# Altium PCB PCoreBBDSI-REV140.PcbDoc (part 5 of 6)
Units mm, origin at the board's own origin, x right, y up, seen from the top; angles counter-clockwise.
Board outline 100 x 72 mm, 6 copper layers (Top Layer, Int1 (GND), Int2 (Sign), Int3 (Sign), Int4 (GND), Bottom Layer), stack 1.551 mm thick; 358 components, 403 nets, 1535 pads, 844 vias.
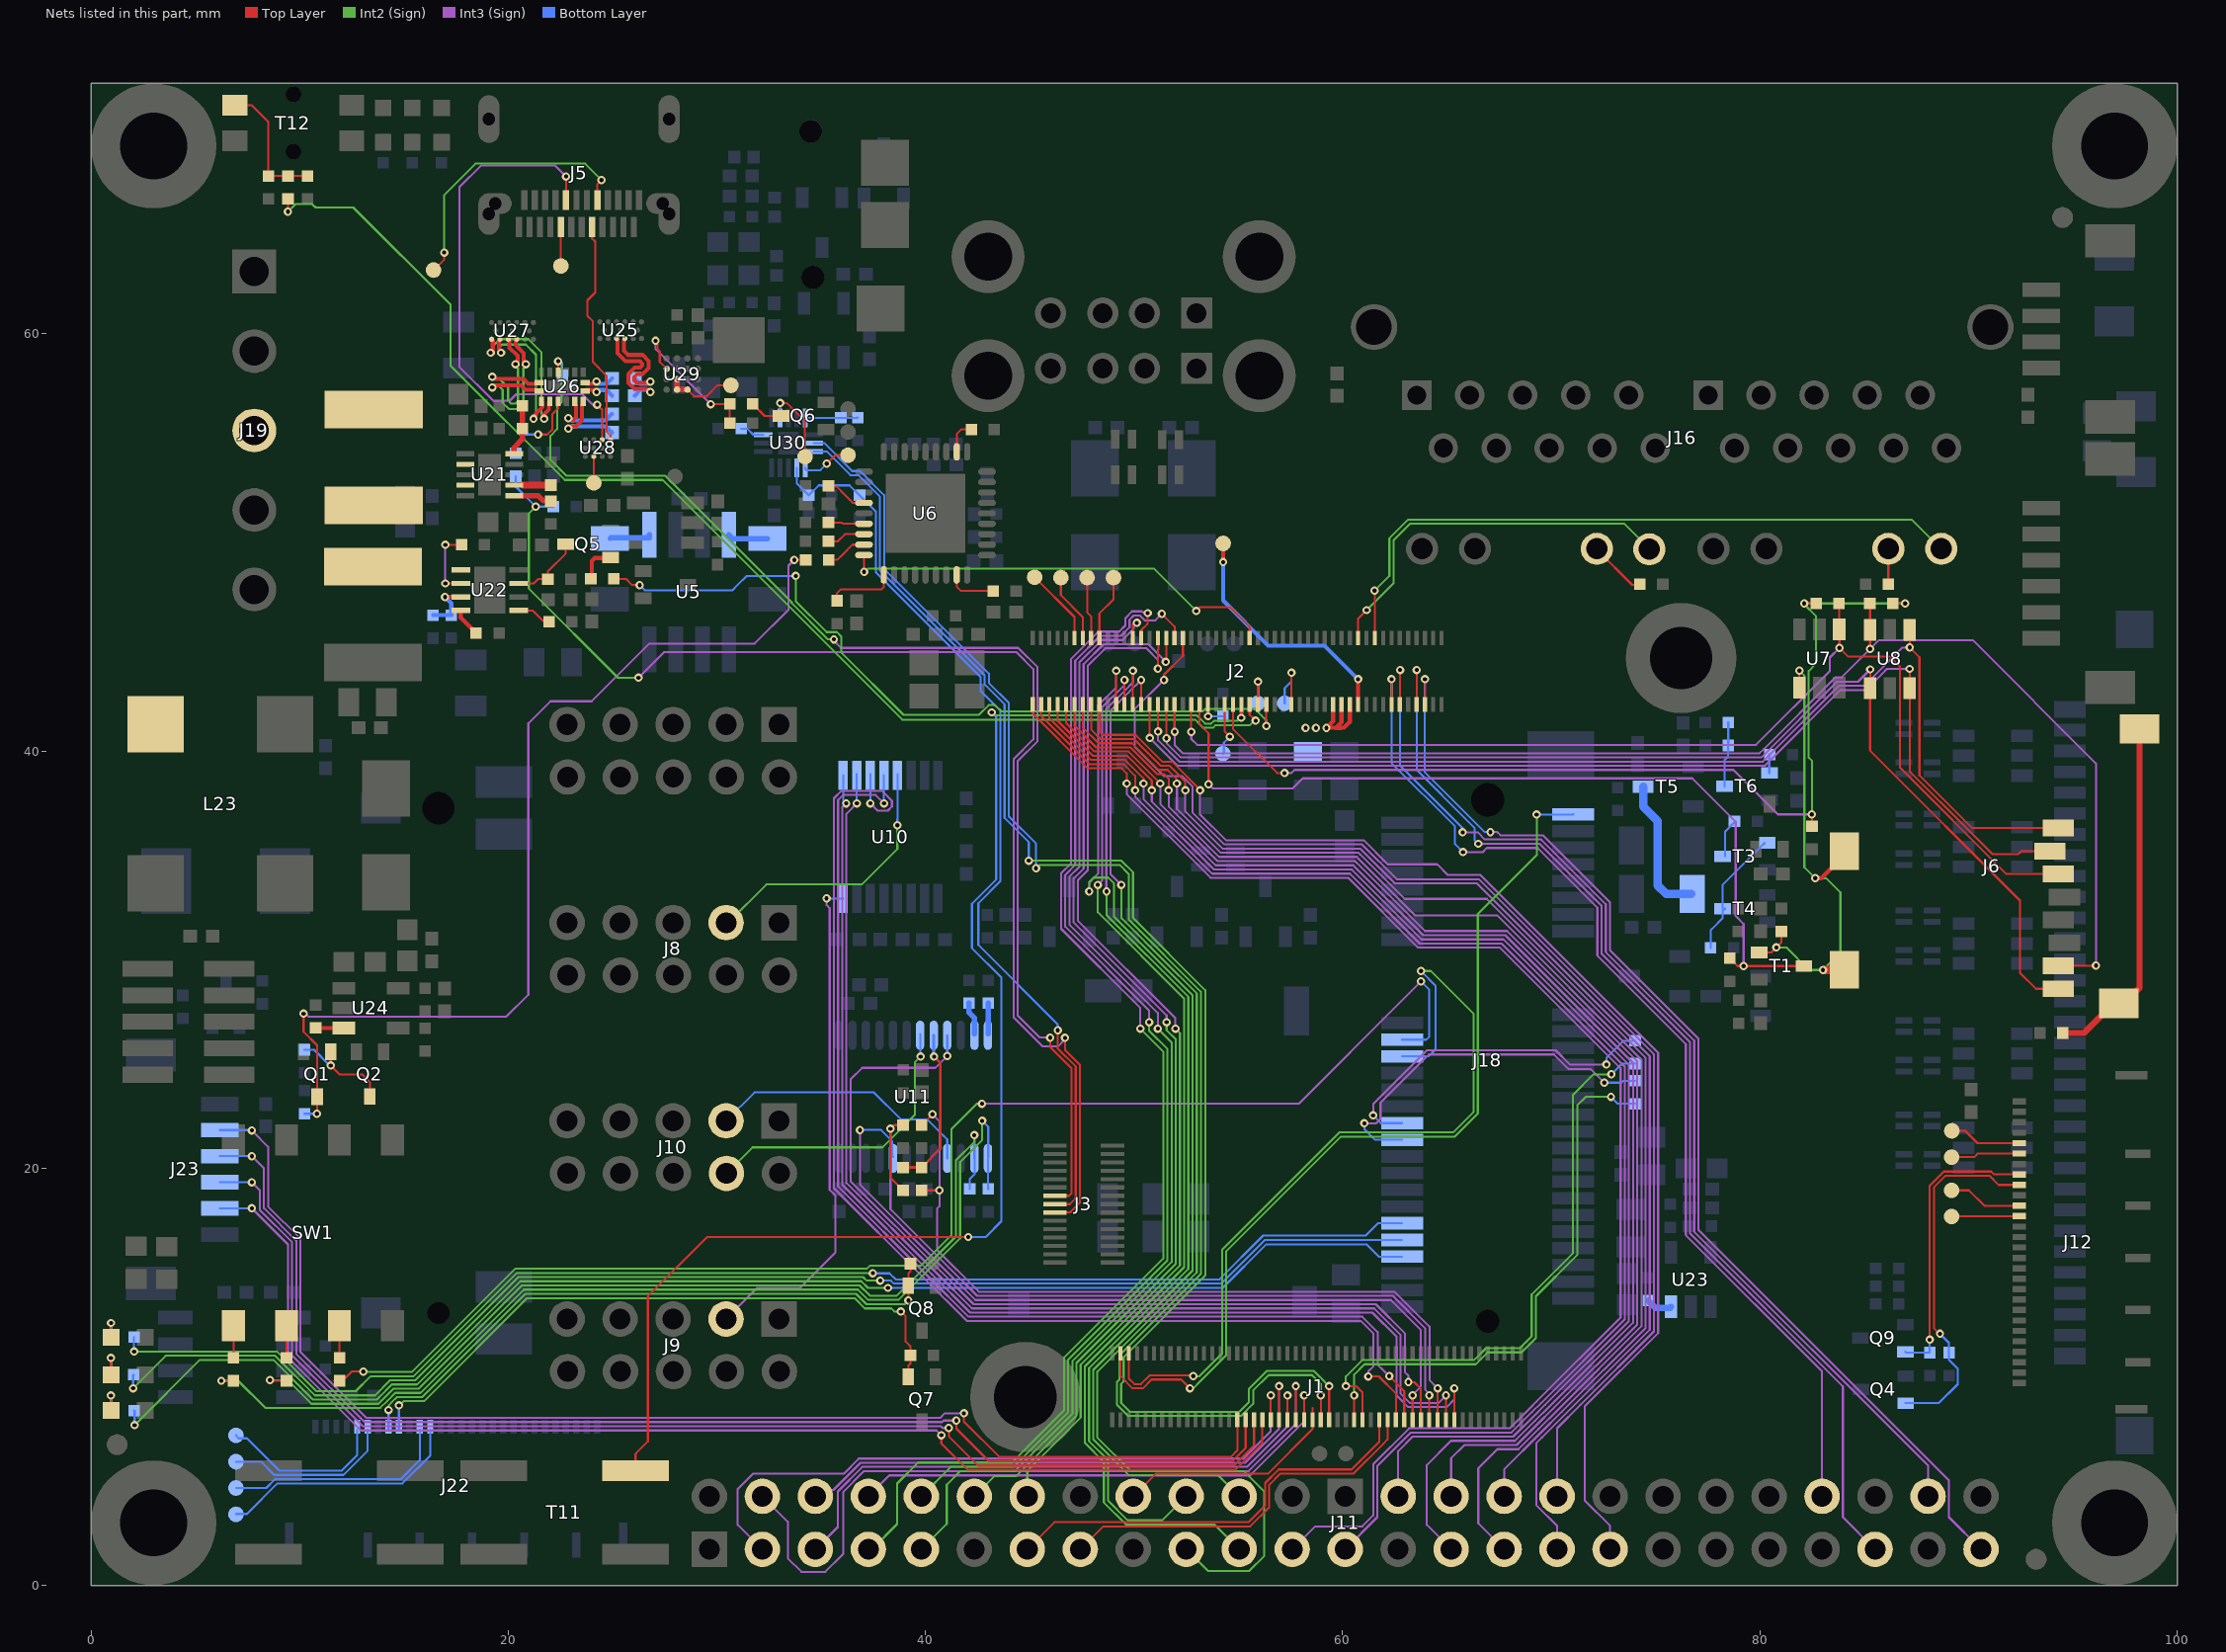
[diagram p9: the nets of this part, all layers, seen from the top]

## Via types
v1: diameter 0.4, hole 0.2, Top Layer to Bottom Layer, tented both sides, 716 vias
v2: diameter 0.5, hole 0.3, Top Layer to Bottom Layer, tented both sides, 102 vias
v3: diameter 0.4, hole 0.2, Top Layer to Bottom Layer, tented bottom, 16 vias
v4: diameter 0.9, hole 0.9, Top Layer to Bottom Layer, 6 vias
v5: diameter 0.5, hole 0.5, Top Layer to Bottom Layer, 2 vias
v6: diameter 3.2, hole 3.2, Top Layer to Bottom Layer, tented both sides, 2 vias

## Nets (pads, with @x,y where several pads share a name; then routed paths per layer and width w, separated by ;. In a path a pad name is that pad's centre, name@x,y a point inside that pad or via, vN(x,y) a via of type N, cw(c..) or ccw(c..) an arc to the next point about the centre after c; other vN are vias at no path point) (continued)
NetJ1_18: J1.18 U10.9 | length 57.2
  Top Layer w0.1: J1.18@65.348,8.229 65.35,8.231 v1(65.35,9.45)
  Int3 (Sign) w0.1: 36.01,37.24 36.01,33.241 36.01,32.619 36.01,19.212 40.31,14.913 42.143,13.08 61.42,13.08 62.58,11.92 62.58,9.102 63.132,8.55 64.98,8.55 65.35,8.92 v1(65.35,9.45) ; 36.01,37.24 36.01,37.3 v1(36.2,37.49)
  Bottom Layer w0.1: U10.9@36.055,38.83 36.055,38.42 36.055,37.462 36.172,37.462 v1(36.2,37.49)
NetJ1_20: J1.20 U10.10 | length 55.6
  Top Layer w0.1: J1.20@64.948,8.229 64.95,8.231 v1(64.95,9.11)
  Int3 (Sign) w0.1: v1(36.71,37.49) 36.21,36.99 36.21,33.324 36.21,32.536 36.21,19.295 40.51,14.996 42.225,13.28 61.457,13.28 61.503,13.28 62.78,12.003 62.78,11.957 62.78,11.858 62.78,9.185 63.215,8.75 64.6,8.75 64.95,9.1 v1(64.95,9.11)
  Bottom Layer w0.1: U10.10@36.705,38.88 36.705,37.635 36.71,37.63 v1(36.71,37.49)
NetJ1_22: J1.22 R39.1 R41.1 | length 37.8
  Top Layer w0.1: R41.1@39.815,18.936 v1(40.67,18.936) ; R39.1@39.815,22.064 39.815,22.075 v1(40.33,22.59) ; J1.22@64.548,8.229 64.55,8.231 v1(64.55,9.45)
  Int3 (Sign) w0.1: v1(40.33,22.59) 40.67,22.25 v1(40.67,18.936) 40.67,18.175 40.55,18.055 40.55,16.087 42.557,14.08 62.48,14.08 64.16,12.4 64.16,9.84 v1(64.55,9.45)
NetJ1_24: J1.24 R40.1 R42.1 | length 39.9
  Top Layer w0.1: R40.1@38.925,18.936 38.32,19.541 v1(38.32,21.89) 38.494,22.064 R42.1@38.925,22.064 ; J1.24@64.148,8.229 64.15,8.231 v1(64.15,9.11)
  Int3 (Sign) w0.1: v1(38.32,21.89) 38.32,18.034 41.11,15.244 42.474,13.88 62.397,13.88 63.95,12.327 63.95,9.391 64.15,9.191 v1(64.15,9.11)
NetJ1_26: J1.26 U11.9 | length 44.9
  Top Layer w0.1: v1(63.15,9.75) 63.162,9.738 63.433,9.738 63.75,9.421 J1.26@63.75,8.231
  Int3 (Sign) w0.1: v1(41.04,25.38) 40.469,24.809 36.964,24.809 36.41,24.255 36.41,19.378 40.71,15.079 42.308,13.48 61.54,13.48 61.586,13.48 62.98,12.086 62.98,12.04 62.98,10.224 63.15,10.055 v1(63.15,9.75)
  Bottom Layer w0.1: v1(41.04,25.38) 41.045,25.385 U11.9@41.045,26.37
NetJ1_28: J1.28 U11.20 | length 39.1
  Top Layer w0.1: J1.28@63.348,8.229 63.35,8.231 v1(63.35,9.11)
  Int3 (Sign) w0.1: v1(36.86,21.83) 36.855,21.825 36.855,19.216 40.91,15.161 42.391,13.68 62.314,13.68 63.75,12.244 63.75,9.54 63.35,9.14 v1(63.35,9.11)
  Bottom Layer w0.1: v1(36.86,21.83) 37.87,21.83 38.41,21.29 38.41,20.585 U11.20@38.455,20.54
NetJ1_30: J1.30 U10.12 | length 55.6
  Top Layer w0.1: v1(62.23,10.03) 62.95,9.31 62.95,8.501 J1.30@62.95,8.16
  Int3 (Sign) w0.1: v1(38.01,37.49) 37.61,37.89 36.054,37.89 35.81,37.645 35.81,37.323 35.81,33.158 35.81,32.702 35.81,19.129 40.109,14.83 42.06,12.88 60.941,12.88 61.674,12.147 61.674,10.586 61.93,10.33 v1(62.23,10.03)
  Bottom Layer w0.1: U10.12@38.005,38.83 U10.12@38.005,38.83 38.006,37.684 38.01,37.68 v1(38.01,37.49)
NetJ1_32: J1.32 U10.11 | length 58.3
  Top Layer w0.1: v1(61.23,10.02) 61.73,10.02 62.55,9.2 J1.32@62.55,8.16
  Int3 (Sign) w0.1: v1(37.36,37.49) 37.71,37.14 37.865,37.14 38.155,37.14 38.19,37.14 38.39,37.34 38.39,37.61 37.91,38.09 35.971,38.09 35.61,37.728 35.61,33.075 35.61,32.785 35.61,19.046 39.909,14.747 41.977,12.68 60.858,12.68 61.474,12.064 61.474,10.514 61.23,10.27 v1(61.23,10.02)
  Bottom Layer w0.1: U10.11@37.355,38.88 37.355,37.635 37.36,37.63 v1(37.36,37.49)
NetJ1_34: J1.34 J11.15 | length 18.5
  Top Layer w0.1: J11.15@47.42,1.73 48.52,2.83 55.563,2.83 56.48,3.747 56.48,4.827 57.013,5.36 60.513,5.36 61.95,6.797 62.15,6.997 J1.34@62.15,7.94 ; J1.34@62.148,8.229 J1.34@62.15,8.231
NetJ1_36: J1.36 J11.13 | length 20.7
  Top Layer w0.1: J11.13@44.88,1.73 46.18,3.03 55.48,3.03 56.28,3.83 56.28,4.91 56.93,5.56 60.43,5.56 61.75,6.88 J1.36@61.75,7.94 ; J1.36@61.748,8.229 J1.36@61.75,8.231
NetJ1_40: J1.40 R55.2 | length 28.4
  Top Layer w0.1: v1(60.15,9.55) 60.65,9.55 60.95,9.25 J1.40@60.95,8.231 ; J1.40@60.948,8.229 J1.40@60.95,8.231 ; J1.40@60.95,7.94 J1.40@60.95,8.231
  Int2 (Sign) w0.1: v1(60.15,9.55) 60.15,10.01 60.94,10.8 66.296,10.8 66.866,11.37 68.493,11.37 69.06,11.938 69.06,13.943 71.04,15.923 71.04,23.52 72.02,24.5 v1(72.88,24.5)
  Bottom Layer w0.1: v1(72.88,24.5) 73.39,25.01 R55.2@74.02,25.01
NetJ1_42: J1.42 R56.2 | length 26.4
  Top Layer w0.1: J1.42@60.548,8.229 60.55,8.231 v1(60.55,9.11)
  Int2 (Sign) w0.1: v1(60.55,9.11) 60.55,10.11 61.04,10.6 66.379,10.6 66.949,11.17 68.413,11.17 68.575,11.17 69.26,11.855 69.26,13.86 71.24,15.84 71.24,23.01 71.65,23.42 v1(72.86,23.42)
  Bottom Layer w0.1: v1(72.86,23.42) 73.19,23.09 R56.2@74.02,23.09
NetJ1_48: J1.48 U30.8 | length 71.2
  Top Layer w0.1: J1.48@59.35,8.231 59.348,8.229 59.348,9.548 v1(59.35,9.55)
  Int2 (Sign) w0.1: v1(44.95,34.74) 49.39,34.74 49.95,34.18 49.95,31.995 53.41,28.535 53.41,14.851 49.5,10.941 49.5,9.782 49.377,9.659 49.377,8.746 49.803,8.32 55.037,8.32 55.51,8.793 55.51,9.43 56.363,10.283 58.617,10.283 v1(59.35,9.55)
  Bottom Layer w0.1: U30.8@34.63,54.36 35.264,54.36 36.404,53.22 36.78,53.22 37.82,52.18 37.82,51.52 37.82,50.973 37.82,48.647 42.84,43.627 42.84,43.182 43.79,42.232 43.79,36.79 44.95,35.63 v1(44.95,34.74)
NetJ1_50: J1.50 U30.7 | length 71.3
  Top Layer w0.1: J1.50@58.948,8.229 58.95,8.231 v1(58.95,9.11)
  Int2 (Sign) w0.1: v1(45.3,34.38) 45.302,34.38 45.462,34.54 49.307,34.54 49.75,34.097 49.75,31.912 53.2,28.461 53.2,14.924 49.3,11.024 49.3,9.865 49.177,9.742 49.177,8.663 49.72,8.12 55.12,8.12 55.71,8.71 55.71,9.347 56.445,10.082 58.534,10.082 58.95,9.667 v1(58.95,9.11)
  Bottom Layer w0.1: U30.7@34.63,54.76 35.147,54.76 36.487,53.42 36.863,53.42 38.02,52.263 38.02,48.73 43.04,43.71 43.04,43.265 43.99,42.315 43.99,36.873 45.3,35.563 v1(45.3,34.38)
NetJ1_52: J1.52 J11.18 | length 10.9
  Top Layer w0.1: J11.18@49.96,4.27 51.04,5.35 56.41,5.35 58.55,7.49 58.55,7.628 J1.52@58.55,7.94 ; J1.52@58.548,7.94 58.548,8.501
NetJ1_54: J1.54 J11.8 | length 24.8
  Top Layer w0.1: J1.54@58.148,8.229 58.148,8.75 ; v1@58.148,9.048 58.148,8.75 ; v1(58.15,9.11) 58.15,8.752 58.148,8.75
  Int3 (Sign) w0.1: J11.8@37.26,4.27 38.262,5.272 39.05,5.272 ; 39.05,5.272 55.562,5.272 58.15,7.86 v1(58.15,9.11)
  Bottom Layer w0.1: J11.8@37.25,4.28 J11.8@37.26,4.27
NetJ1_56: J1.56 J11.4 | length 35.9
  Top Layer w0.1: J1.56@57.748,8.229 57.748,9.548 v1(57.75,9.55)
  Int3 (Sign) w0.1: J11.4@32.18,4.27 33.4,3.05 33.4,1.3 34.05,0.65 35.2,0.65 36.05,1.5 36.05,4.474 37.056,5.48 40.409,5.48 55.487,5.48 57.75,7.743 v1(57.75,9.55)
NetJ1_58: J1.58 J11.5 | length 28.4
  Top Layer w0.1: J1.58@57.348,8.229 57.348,9.098 v1(57.35,9.1)
  Int3 (Sign) w0.1: J11.5@34.72,1.73 34.73,1.73 35.8,2.8 35.8,4.507 36.973,5.68 40.492,5.68 55.404,5.68 57.35,7.626 v1(57.35,9.1)
NetJ1_60: J1.60 J11.6 | length 26.9
  Top Layer w0.1: J1.60@56.948,8.229 56.95,8.231 v1(56.95,9.55)
  Int3 (Sign) w0.1: J11.6@34.72,4.27 35.026,4.576 35.586,4.576 36.89,5.88 40.575,5.88 55.321,5.88 56.95,7.509 v1(56.95,9.55)
NetJ1_62: J1.62 J11.3 | length 36.8
  Top Layer w0.1: 56.548,8.752 56.548,8.229 56.55,8.231 v1(56.55,9.11) ; 56.55,8.752 v1(56.55,9.11) ; 56.55,8.752 v1(56.55,9.11) ; 56.55,8.752 v1(56.55,9.11) ; 56.55,8.752 v1(56.55,9.11) ; 56.55,8.752 v1(56.55,9.11) ; 56.55,8.752 v1(56.55,9.11) ; 56.55,8.752 v1(56.55,9.11) ; 56.55,8.752 v1(56.55,9.11) ; 56.55,8.752 v1(56.55,9.11) ; 56.55,8.752 v1(56.55,9.11)
  Int3 (Sign) w0.1: J11.3@32.18,1.73 32.17,1.73 31,2.9 31,4.62 31.74,5.36 36.087,5.36 36.807,6.08 40.657,6.08 55.238,6.08 56.55,7.392 v1(56.55,9.11)
NetJ1_64: J1.64 J23.5 | length 60.3
  Top Layer w0.1: v1(40.76,7.2) 40.76,6.8 42.01,5.55 54.877,5.55 56.148,6.821 J1.64@56.148,8.229
  Int3 (Sign) w0.1: v1(7.71,18.075) 9.44,16.345 9.44,10.936 10.05,10.326 10.05,10.323 12.943,7.43 40.53,7.43 v1(40.76,7.2)
  Bottom Layer w0.1: J23.5@6.17,18.075 7.47,18.075
NetJ1_66: J1.66 J23.4 | length 60.9
  Top Layer w0.1: v1(41.12,7.55) 41.12,7.15 42.52,5.75 54.794,5.75 55.748,6.704 J1.66@55.748,8.229
  Int3 (Sign) w0.1: v1(7.71,19.325) 8.09,18.945 8.09,17.994 9.64,16.444 9.64,11.019 13.029,7.63 40.74,7.63 40.82,7.55 v1(41.12,7.55)
  Bottom Layer w0.1: J23.4@6.17,19.325 7.47,19.325
NetJ1_68: J1.68 J23.3 | length 61.5
  Top Layer w0.1: v1(41.48,7.9) 41.48,7.515 43.045,5.95 54.711,5.95 55.348,6.587 J1.68@55.348,8.229
  Int3 (Sign) w0.1: v1(7.71,20.575) 8.29,19.995 8.29,18.077 9.84,16.527 9.84,11.102 13.112,7.83 40.793,7.83 40.863,7.9 v1(41.48,7.9)
  Bottom Layer w0.1: J23.3@6.17,20.575 7.47,20.575
NetJ1_70: J1.70 J23.2 | length 62.4
  Top Layer w0.1: v1(41.84,8.25) 41.84,7.862 43.552,6.15 54.628,6.15 54.948,6.47 J1.70@54.948,8.229
  Int3 (Sign) w0.1: v1(7.71,21.81) 8.49,21.03 8.49,18.16 10.04,16.61 10.04,11.185 13.195,8.03 40.71,8.03 40.93,8.25 v1(41.84,8.25)
  Bottom Layer w0.1: J23.2@6.17,21.825 7.695,21.825 v1(7.71,21.81)
NetJ1_95: J1.95 J18.22 | length 40.1
  Top Layer w0.1: J1.95@49.75,11.12 49.75,9.915 50.015,9.65 50.335,9.65 50.755,10.07 52.83,10.07 52.84,10.08 52.84,10.032 v1(52.838,10.03)
  Int2 (Sign) w0.1: v1(52.838,10.03) 53.13,10.03 54.22,11.12 54.22,16.1 59.835,21.715 65.295,21.715 66.28,22.7 66.28,27.39 64.22,29.45 v1(63.75,29.45)
  Bottom Layer w0.1: J18.22@62.85,25.36 64.11,25.36 64.45,25.7 64.45,28.749 v1(63.75,29.45)
NetJ1_97: J1.97 J18.1 | length 44.4
  Top Layer w0.1: J1.97@49.35,11.12 49.35,10.032 49.932,9.45 50.418,9.45 50.838,9.87 52.26,9.87 v1(52.68,9.45)
  Int2 (Sign) w0.1: v1(52.68,9.45) 52.833,9.45 53.213,9.83 54.42,11.037 54.42,16.017 59.918,21.515 65.378,21.515 66.48,22.617 66.48,32.186 69.3,35.006 v1(69.3,36.95)
  Bottom Layer w0.1: v1(69.3,36.95) 71.04,36.95 J18.1@71.05,36.96
NetJ2_6: J2.6 J11.49 | length 55.2
  Top Layer w0.1: 63.94,42.791 63.95,42.801 v1@63.95,43.44 ; J2.6@63.95,42.507 63.95,42.791
  Int3 (Sign) w0.1: v1(67.08,36.11) 67.41,36.11 67.56,35.96 69.589,35.96 72.81,32.739 72.81,30.442 77.05,26.202 77.05,17.079 ; 77.05,17.079 77.05,17.04 89.06,5.03 89.06,3.27 J11.49@90.6,1.73
  Bottom Layer w0.1: v1(63.94,43.44) 63.94,38.978 66.2,36.718 66.807,36.11 v1(67.08,36.11)
NetJ2_8: J2.8 J11.45 | length 54.3
  Top Layer w0.1: J2.8@63.538,42.519 63.55,42.531 63.55,43.44 v1(63.55,43.88)
  Int3 (Sign) w0.1: v1(66.5,35.55) 69.433,35.55 72.41,32.573 72.41,30.276 76.65,26.036 76.65,16.913 76.65,16.874 83.98,9.544 83.98,3.27 J11.45@85.52,1.73
  Bottom Layer w0.1: v1(63.55,43.88) 63.55,43.44 63.55,39.085 66,36.635 66.32,36.314 66.32,35.73 v1(66.5,35.55)
NetJ2_12: J2.12 J11.48 | length 53.5
  Top Layer w0.1: J2.12@62.738,42.519 62.75,42.531 v1(62.75,43.88)
  Int3 (Sign) w0.1: v1(65.75,36.1) 66.47,36.1 66.81,35.76 69.506,35.76 72.61,32.656 72.61,30.359 76.85,26.119 76.85,16.996 ; 76.85,16.996 76.85,16.957 88.06,5.747 J11.48@88.06,4.27
  Bottom Layer w0.1: v1(62.75,43.88) 62.75,39.31 65.75,36.31 v1(65.75,36.1)
NetJ2_14: J2.14 J11.44 | length 51.1
  Top Layer w0.1: J2.14@62.338,42.519 J2.14@62.34,42.517 ; v1(62.34,43.44) J2.14@62.34,42.517 ; J2.14@62.34,42.517 62.35,42.507 J2.14@62.34,42.517
  Int3 (Sign) w0.1: v1(65.77,35.15) 66.71,35.15 66.91,35.35 69.35,35.35 72.21,32.49 72.21,30.193 76.45,25.953 76.45,16.83 76.45,16.791 82.98,10.261 J11.44@82.98,4.27
  Bottom Layer w0.1: v1(62.34,43.44) 62.34,39.43 65.38,36.39 65.38,35.54 v1(65.77,35.15)
NetJ2_17: J2.17 J16.L14 | length 32.8
  Top Layer w0.1: v1(61.53,47.69) 61.538,47.682 J2.17@61.538,45.129
  Int2 (Sign) w0.1: v1(61.53,47.69) 61.53,47.68 62.24,48.39 62.24,50.193 63.137,51.09 87.275,51.09 J16.L14@88.695,49.67
NetJ2_21: J2.21 J16.R14 | length 18.8
  Top Layer w0.1: J2.21@60.738,45.129 60.738,46.338 v1(61.15,46.75)
  Int2 (Sign) w0.1: v1(61.15,46.75) 62.44,48.04 62.44,50.11 63.22,50.89 73.505,50.89 J16.R14@74.725,49.67
NetJ2_22: J2.22 TP1.1 | length 11.7
  Top Layer w0.2: v1(54.27,49.05) TP1.1@54.27,49.95 ; J2.22@60.738,42.519 v1(60.738,43.44)
  Bottom Layer w0.2: v1(54.27,49.05) 54.27,47.21 56.43,45.05 59.128,45.05 v1(60.738,43.44)
NetJ2_24: J2.24 J2.26 J2.28 R2.1 | length 5.3
  Top Layer w0.2: J2.28@59.54,42.45 59.54,41.42 v1(59.22,41.1) 59.23,41.11 59.67,41.11 ; J2.26@59.94,42.45 59.94,41.38 59.66,41.1 59.914,41.1 59.924,41.11 60.06,41.11 60.34,41.39 J2.24@60.34,42.45
  other v1: 58.22,41.1 58.72,41.1
NetJ2_38: J2.38 TP29.1 | length 3.1
  Top Layer w0.1: J2.38@57.54,42.23 v1@57.54,43.76
  Bottom Layer w0.1: TP29.1@57.22,42.29 57.22,43.01 57.54,43.33 v1@57.54,43.76
  other v1: 57.54,43.75
NetJ2_44: J2.44 R79.1 | length 37.9
  Top Layer w0.1: R79.1@25.06,48.25 25.64,48.25 25.94,47.95 v1(26.3,47.95) ; J2.44@56.338,42.519 56.338,41.2 v1(56.34,41.2)
  Int2 (Sign) w0.1: v1(33.782,48.387) 33.782,47.178 35.26,45.7 35.755,45.7 35.96,45.495 35.96,44.72 38.95,41.73 42.565,41.73 43.035,42.2 43.34,42.2 43.64,41.9 53.297,41.9 53.406,42.01 55.8,42.01 56.11,41.7 56.34,41.47 v1(56.34,41.2)
  Bottom Layer w0.1: v1(26.3,47.95) 26.56,47.69 30.728,47.69 30.988,47.95 31.425,48.387 v1(33.782,48.387)
NetJ2_46: J2.46 TP23.1 | length 2.1
  Top Layer w0.1: J2.46@55.94,42.23 v1(55.94,43.32)
  Bottom Layer w0.1: TP23.1@55.92,42.29 55.94,42.31 v1(55.94,43.32)
NetJ2_47: J2.47 U6.27 | length 21.5
  Top Layer w0.1: U6.27@37,49.39 37.084,49.306 37.06,49.282 v1(37.06,48.59) ; v1(52.98,46.71) 53.16,46.89 53.935,46.89 54.6,46.89 55.2,46.29 55.538,45.952 J2.47@55.538,45.129
  Int2 (Sign) w0.1: v1(37.06,48.59) 37.06,48.566 37.064,48.57 37.239,48.745 50.945,48.745 v1(52.98,46.71)
NetJ2_48: J2.48 R70.2 | length 60.6
  Top Layer w0.1: v1(9.44,65.85) R70.2@9.44,66.46 ; J2.48@55.54,42.517 55.538,42.519 55.538,41.742 v1(55.83,41.45)
  Int2 (Sign) w0.1: v1(9.44,65.85) 9.8,66.21 10.605,66.21 10.765,66.05 11.223,66.05 12.038,66.05 12.57,66.05 17.23,61.39 17.23,59.498 17.23,59.042 17.23,58.467 22.707,52.99 26.925,52.99 27.215,52.99 27.4,52.99 38.89,41.5 52.933,41.5 53.128,41.305 53.324,41.109 53.779,41.109 53.91,41.24 55.557,41.24 55.767,41.45 v1(55.83,41.45)
NetJ2_50: J2.50 T11.2 | length 65.8
  Top Layer w0.1: T11.2@26.1,5.5 26.1,6.31 26.695,6.905 26.695,13.865 29.53,16.7 v1(42.05,16.7) ; v1(55.13,41.59) 55.13,41.57 v1@55.14,41.56
  Top Layer w0.2: v1@55.14,41.56 J2.50@55.14,42.23 J2.50@55.14,42.45
  Int2 (Sign) w0.1: v1(43.18,41.85) 43.222,41.85 43.372,41.7 43.557,41.7 53.016,41.7 53.406,41.309 53.696,41.309 53.827,41.44 54.958,41.44 55.108,41.59 v1(55.13,41.59)
  Bottom Layer w0.1: v1(42.05,16.7) 42.885,16.7 43.64,17.455 43.64,26.377 43.64,29.14 42.23,30.55 42.23,32.68 43.39,33.84 43.39,41.638 v1(43.18,41.85) v1(43.18,41.85)
NetJ2_52: J2.52 R23.2 R24.2 R29.2 | length 48.2
  Top Layer w0.1: J2.52@54.738,42.519 54.738,41.062 56.86,38.94 v1(57.21,38.94) ; v1(82.12,47.07) 82.68,47.07 R24.2@82.69,47.08 ; v1(82.49,36.96) 82.49,36.35 R29.2@82.5,36.34 ; R23.2@86.37,47.08 86.95,47.08 v1(86.96,47.07)
  Int2 (Sign) w0.1: v1(82.49,36.96) 82.49,39.535 82.34,39.685 82.34,43.835 82.683,44.178 82.683,46.474 82.12,47.037 v1(82.12,47.07) v1(86.96,47.07)
  Int3 (Sign) w0.1: v1(57.21,38.94) 57.54,38.94 57.69,39.09 78.733,39.09 80.864,36.96 v1@82.458,36.96
NetJ2_58: J2.58 R22.1 | length 1.6
  Top Layer w0.1: J2.58@53.538,42.519 53.546,42.511 53.546,41.665 v1(53.551,41.659)
  Bottom Layer w0.1: v1(53.551,41.659) R22.1@54.259,41.659
NetJ2_60: J2.60 R21.1 T1.3 | length 41.5
  Top Layer w0.1: J2.60@53.138,42.519 53.138,41.272 53.57,40.84 v1@53.57,38.41 ; R21.1@78.56,30.06 78.93,29.69 v1(79.22,29.69) T1.3@82.105,29.69
  Int3 (Sign) w0.1: v1@53.57,38.41 53.78,38.2 57.59,38.2 58.08,38.69 76.755,38.69 78.84,36.605 78.84,32.09 79.22,31.71 v1(79.22,29.69)
  other v1: 53.57,38.406
NetJ2_62: J2.62 J6.3 R24.1 U7.4 | length 55.4
  Top Layer w0.1: J2.62@52.738,42.519 52.738,40.917 v1(52.74,40.915) ; R24.1@83.79,47.08 83.8,47.07 U7.4@83.8,45.83 83.81,45.82 v1(83.81,44.94) 84.22,44.53 86.22,44.53 86.72,44.03 86.72,39.194 91.814,34.1 J6.3@94.3,34.1
  Int3 (Sign) w0.1: v1(52.74,40.915) 52.74,40.569 53.019,40.29 56.651,40.29 79.816,40.291 83.35,43.825 83.35,44.48 v1(83.81,44.94)
NetJ2_63: J2.63 J11.34 | length 60.8
  Top Layer w0.1: v1(51.43,43.4) 51.43,43.65 52.34,44.56 52.34,44.849 J2.63@52.34,45.19
  Int3 (Sign) w0.1: v1@51.45,43.43 50.04,42.02 50.04,40.19 51.43,38.8 52.3,38.8 52.81,38.29 52.81,37.034 54.323,35.521 60.923,35.521 62.593,33.85 66.527,33.85 74.9,25.477 74.9,25.469 74.921,25.448 74.921,12.179 71.4,8.658 70.28,7.539 J11.34@70.28,4.27
NetJ2_65: J2.65 J11.10 | length 55.8
  Top Layer w0.1: v1(51.33,46.57) 51.94,45.96 51.94,45.795 J2.65@51.94,45.41
  Int2 (Sign) w0.1: J11.10@39.8,4.27 41.21,5.68 44.213,5.68 46.84,8.307 46.84,10.827 51.6,15.587 51.6,25.71 50.72,26.59 v1(50.72,27)
  Int3 (Sign) w0.1: v1(50.72,27) 50.72,27.56 46.7,31.58 46.7,34.057 47.18,34.537 47.18,44.328 48.372,45.52 49.368,45.52 49.78,45.932 49.78,46.285 49.985,46.49 50.275,46.49 50.505,46.26 51.02,46.26 v1(51.33,46.57)
NetJ2_66: J2.66 J6.7 R23.1 U8.6 | length 65
  Top Layer w0.1: J2.66@51.938,42.519 51.938,40.915 v1@51.953,40.9 ; R23.1@85.27,47.08 85.28,47.07 U8.6@85.28,45.81 v1(85.28,44.89) ; J6.7@94.3,29.7 94.31,29.71 v1(96.11,29.71)
  Int3 (Sign) w0.1: v1(51.95,40.92) 51.95,40.269 52.329,39.89 56.817,39.89 79.982,39.89 80.182,40.09 83.611,43.52 83.91,43.52 v1(85.28,44.89) 85.7,45.31 90.2,45.31 96.11,39.4 v1(96.11,29.71)
NetJ2_67: J2.67 J11.12 | length 52.6
  Top Layer w0.1: v1(51.52,44.27) 51.54,44.29 J2.67@51.54,45.41
  Int2 (Sign) w0.1: J11.12@42.34,4.27 43.3,5.23 44.33,5.23 47.24,8.14 47.24,10.661 52,15.421 52,26.175 51.56,26.615 v1(51.56,27)
  Int3 (Sign) w0.1: v1(51.52,44.27) 51.52,44.28 50.68,45.12 48.538,45.12 47.58,44.162 47.58,34.36 47.1,33.88 47.1,31.78 51.56,27.32 v1(51.56,27)
NetJ2_68: J2.68 J6.8 U8.1 | length 57.6
  Top Layer w0.1: J2.68@51.55,42.507 51.55,40.603 v1(51.551,40.602) ; v1(85.29,43.91) 85.29,43.02 U8.1@85.28,43.01 85.28,40.02 92.47,32.83 92.47,29.36 93.23,28.6 93.979,28.6 J6.8@94.3,28.6
  Int3 (Sign) w0.1: v1(51.551,40.602) 51.562,40.591 51.562,40.374 52.246,39.69 56.899,39.69 80.064,39.69 83.694,43.32 84.7,43.32 v1(85.29,43.91)
NetJ2_69: J2.69 J11.14 | length 50.9
  Top Layer w0.1: v1(51.14,43.94) 51.14,44.848 ; J2.69@51.14,45.41 51.16,45.39 51.16,44.849
  Int2 (Sign) w0.1: J11.14@44.88,4.27 44.88,5.49 47.44,8.05 47.44,10.578 52.2,15.339 52.2,26.47 v1(51.98,26.69)
  Int3 (Sign) w0.1: v1@51.16,43.96 51.14,43.98 51.14,44.377 50.597,44.92 48.62,44.92 47.78,44.08 47.78,34.277 47.3,33.797 47.3,31.87 51.98,27.19 v1(51.98,26.69)
NetJ2_70: J2.70 J6.1 U8.4 | length 55.5
  Top Layer w0.1: J2.70@51.14,42.45 51.14,40.94 v1(51.15,40.93) ; U8.4@87.18,45.81 v1(87.18,44.96) 87.65,44.49 87.65,38.83 90.18,36.3 J6.1@94.3,36.3
  Int3 (Sign) w0.1: v1(51.15,40.93) 51.15,40.503 52.163,39.49 56.982,39.49 57.438,39.49 57.524,39.49 80.147,39.49 83.777,43.12 84.995,43.12 86.83,44.955 87.175,44.955 v1(87.18,44.96)
NetJ2_72: J2.72 J6.2 U8.3 | length 54.1
  Top Layer w0.1: J2.72@50.74,42.501 50.74,40.63 v1(50.75,40.62) ; v1(87.178,43.933) 87.18,43.931 U8.3@87.18,43.01 87.18,39.017 90.097,36.1 91.145,35.052 92.392,35.052 92.54,35.2 J6.2@93.9,35.2
  Int3 (Sign) w0.1: v1(50.75,40.62) 52.08,39.29 57.065,39.29 57.355,39.29 57.607,39.29 80.23,39.29 83.86,42.92 85.078,42.92 85.84,43.682 86.091,43.933 v1(87.178,43.933)
NetJ2_73: J2.73 J11.7 | length 59.7
  Top Layer w0.1: J2.73@50.34,45.41 50.34,45.79 50.65,46.1 v1(50.65,46.61)
  Int2 (Sign) w0.1: J11.7@37.26,1.73 37.43,1.73 38.64,2.94 38.64,4.88 39.65,5.89 44.14,5.89 45.62,7.37 46.64,8.39 46.64,10.91 51.4,15.67 51.4,25.59 v1(50.3,26.69)
  Int3 (Sign) w0.1: v1(50.3,26.69) 50.3,27.68 46.5,31.48 46.5,34.14 46.98,34.62 46.98,44.411 48.289,45.72 49.285,45.72 49.58,46.015 49.58,46.368 49.902,46.69 50.358,46.69 50.4,46.648 50.612,46.648 v1(50.65,46.61)
NetJ2_74: J2.74 J11.19 | length 58.1
  Top Layer w0.1: J2.74@50.338,42.519 v1(50.338,43.4)
  Int2 (Sign) w0.1: v1(49.39,33.58) 49.39,31.989 49.59,31.789 51.38,29.999 53,28.379 53,15.007 48.24,10.247 48.24,7.08 49.84,5.48 55.244,5.48 56.24,4.484 56.24,1.41 55.52,0.69 53.54,0.69 J11.19@52.5,1.73
  Int3 (Sign) w0.1: v1(49.39,33.58) 48.87,34.1 48.87,41.932 49.74,42.802 v1(50.338,43.4)
NetJ2_75: J2.75 J11.9 | length 55.7
  Top Layer w0.1: J2.75@49.94,45.41 49.94,46.065 49.957,46.083 50.115,46.083 v1@50.13,46.097
  Int2 (Sign) w0.1: J11.9@39.8,1.73 41.02,2.95 41.02,4.83 41.67,5.48 44.296,5.48 47.04,8.224 47.04,10.744 51.8,15.504 51.8,26.03 51.36,26.47 v1(51.14,26.69)
  Int3 (Sign) w0.1: v1(50.13,46.14) 50.13,46.086 49.98,45.936 49.98,45.849 49.451,45.32 48.455,45.32 47.38,44.245 47.38,34.45 46.9,33.97 46.9,31.68 51.14,27.44 v1(51.14,26.69)
NetJ2_76: J2.76 J11.20 | length 50.2
  Top Layer w0.1: J2.76@49.938,42.519 J2.76@49.938,42.562 ; v1(49.938,43.84) J2.76@49.938,42.562 ; J2.76@49.95,42.55 J2.76@49.938,42.562
  Int2 (Sign) w0.1: v1(48.68,33.27) 48.68,32.133 52.6,28.213 52.6,15.173 47.84,10.413 47.84,6.914 48.76,5.994 48.76,4.056 49.696,3.12 51.35,3.12 J11.20@52.5,4.27
  Int3 (Sign) w0.1: v1(48.68,33.27) 48.67,33.28 48.67,42.015 49.54,42.885 49.95,43.295 49.95,43.828 v1(49.938,43.84)
NetJ2_78: J2.78 J11.21 | length 52.3
  Top Layer w0.1: J2.78@49.538,42.519 v1(49.538,43.4)
  Int2 (Sign) w0.1: v1(48.26,33.58) 48.26,32.27 52.4,28.13 52.4,15.256 47.64,10.496 47.64,6.831 48.55,5.921 48.55,3.98 49.61,2.92 51.94,2.92 53.85,2.92 J11.21@55.04,1.73
  Int3 (Sign) w0.1: v1(48.26,33.58) 48.47,33.79 48.47,42.098 49.538,43.166 v1(49.538,43.4)
NetJ2_80: J2.80 J11.22 | length 52.6
  Top Layer w0.1: J2.80@49.138,42.519 v1(49.138,43.84)
  Int2 (Sign) w0.1: v1(47.85,33.27) 47.85,33.72 48.06,33.93 48.76,33.93 49.03,33.66 49.03,33.415 49.03,33.125 49.03,32.066 51.18,29.916 52.8,28.296 52.8,15.09 48.04,10.33 48.04,6.997 49.757,5.28 54.03,5.28 J11.22@55.04,4.27
  Int3 (Sign) w0.1: v1(47.85,33.27) 47.85,33.69 48.27,34.11 48.27,42.181 49.138,43.048 v1@49.138,43.839
NetJ2_84: J2.84 J11.35 | length 61.2
  Top Layer w0.1: J2.84@48.34,42.45 48.34,40.92 48.49,40.77 50.07,40.77 51.35,39.49 51.82,39.49 53.2,38.11 v1(53.16,38.11)
  Int3 (Sign) w0.1: v1(53.16,38.11) 53.16,36.966 54.406,35.721 61.006,35.721 62.156,34.57 64.53,34.57 65.04,34.06 66.6,34.06 75.1,25.56 75.1,25.551 75.121,25.531 75.121,12.096 71.6,8.576 71.6,4.076 72.82,2.856 J11.35@72.82,1.73
NetJ2_86: J2.86 J11.33 | length 61.8
  Top Layer w0.1: J2.86@47.94,42.45 47.94,41.027 48.397,40.57 49.987,40.57 51.267,39.29 51.701,39.29 52.455,38.536 v1@52.455,38.106
  Int3 (Sign) w0.1: v1@52.455,38.106 52.455,37.106 54.24,35.321 60.84,35.321 60.92,35.241 62.511,33.65 66.444,33.65 74.7,25.394 74.7,25.386 74.721,25.365 74.721,12.262 70.701,8.242 69.558,7.099 69.28,6.821 69.28,3.856 70.28,2.856 J11.33@70.28,1.73
  other v1: 52.455,38.11
NetJ2_88: J2.88 J11.32 | length 59.5
  Top Layer w0.1: J2.88@47.54,42.45 47.54,41.13 48.3,40.37 49.904,40.37 51.184,39.09 51.61,39.09 52.011,38.689 52.011,38.445 v1@52.049,38.406
  Int3 (Sign) w0.1: v1@52.049,38.406 52.057,38.399 52.057,37.221 54.157,35.12 60.757,35.12 60.837,35.04 62.968,32.91 66.901,32.91 74.5,25.311 74.5,25.303 74.52,25.282 74.52,12.345 70.501,8.325 69.475,7.299 67.74,5.564 J11.32@67.74,4.27
  other v1: 52.049,38.44
NetJ2_90: J2.90 J11.31 | length 63.7
  Top Layer w0.1: J2.90@47.14,42.45 47.14,41.215 48.185,40.17 49.821,40.17 51.101,38.89 51.44,38.89 51.658,38.672 51.658,38.116 v1@51.649,38.107
  Int3 (Sign) w0.1: v1@51.649,38.107 51.658,38.098 51.658,37.337 54.074,34.92 60.674,34.92 60.754,34.84 63.485,32.11 67.418,32.11 74.3,25.228 74.3,25.22 74.32,25.199 74.32,12.428 70.3,8.408 69.392,7.5 68.422,6.529 67.409,6.529 66.5,5.62 66.5,2.97 J11.31@67.74,1.73
  other v1: 51.649,38.11
NetJ2_92: J2.92 J11.30 | length 61.8
  Top Layer w0.1: J2.92@46.74,42.45 46.74,41.332 48.102,39.97 49.739,39.97 51.255,38.453 v1(51.255,38.44)
  Int3 (Sign) w0.1: v1(51.255,38.44) 51.257,38.438 51.257,37.455 53.991,34.72 60.591,34.72 60.671,34.64 63.942,31.37 67.875,31.37 74.1,25.146 74.1,25.137 74.12,25.117 74.12,12.511 70.1,8.491 69.309,7.7 68.339,6.73 65.83,6.73 65.2,6.1 J11.30@65.2,4.27
NetJ2_94: J2.94 J11.29 | length 65.6
  Top Layer w0.1: J2.94@46.34,42.45 46.34,41.449 48.019,39.77 49.656,39.77 50.847,38.578 v1@50.847,38.092
  Int3 (Sign) w0.1: v1@50.847,38.092 50.847,37.582 53.909,34.52 60.509,34.52 60.589,34.44 63.859,31.17 67.594,31.17 67.789,31.17 73.9,25.059 73.9,25.054 73.92,25.034 73.92,12.593 69.9,8.574 69.226,7.9 68.256,6.93 65.19,6.93 64.03,5.77 64.03,2.9 J11.29@65.2,1.73
  other v1: 50.847,38.11
NetJ2_96: J2.96 J11.28 | length 64.2
  Top Layer w0.1: J2.96@45.94,42.45 45.94,41.566 47.936,39.57 49.573,39.57 50.451,38.691 v1@50.451,38.428
  Int3 (Sign) w0.1: v1@50.451,38.428 50.451,37.695 53.826,34.32 60.426,34.32 60.506,34.24 63.776,30.97 67.511,30.97 67.706,30.97 73.7,24.976 73.7,24.971 73.72,24.951 73.72,12.676 69.7,8.656 69.144,8.1 68.174,7.13 63.35,7.13 62.66,6.44 J11.28@62.66,4.27
  other v1: 50.451,38.44
NetJ2_98: J2.98 J11.25 | length 67.8
  Top Layer w0.1: J2.98@45.54,42.45 45.54,41.683 47.853,39.369 49.49,39.369 50.05,38.809 v1@50.05,38.1
  Int3 (Sign) w0.1: v1@50.05,38.1 50.05,37.813 53.743,34.12 60.343,34.12 60.423,34.04 63.693,30.77 67.618,30.77 73.43,24.958 73.52,24.868 73.52,12.759 69.5,8.739 69.061,8.3 68.091,7.33 63.267,7.33 61.66,5.723 61.66,3.27 J11.25@60.12,1.73
  other v1: 50.05,38.11
NetJ2_100: J2.100 J11.23 | length 70.2
  Top Layer w0.1: J2.100@45.14,42.45 45.14,41.8 47.771,39.169 49.407,39.169 49.649,38.928 v1@49.649,38.428
  Int3 (Sign) w0.1: v1@49.649,38.428 49.649,37.931 53.66,33.92 60.26,33.92 63.61,30.57 67.535,30.57 73.32,24.785 73.32,12.842 69.3,8.822 68.978,8.5 68.008,7.53 63.184,7.53 61.46,5.806 61.46,3.353 60.937,2.83 58.68,2.83 J11.23@57.58,1.73
  other v1: 49.649,38.44
NetJ3_13: J3.13 R60.2 R95.2 | length 63.5
  Top Layer w0.1: J3.13@46.209,17.876 46.926,17.876 47.4,18.35 47.4,24.959 46.69,25.669 v1(46.69,26.25)
  Int2 (Sign) w0.1: v1(21.32,51.71) 20.985,51.375 20.985,47.785 25.26,43.51 v1(26.24,43.51)
  Int3 (Sign) w0.1: v1(26.24,43.51) 27.47,44.74 44.357,44.74 45.17,43.927 45.17,40.553 44.22,39.603 44.22,27.24 45.624,25.836 46.346,25.836 46.69,26.18 v1(46.69,26.25)
  Bottom Layer w0.1: R95.2@20.36,53.17 20.36,52.67 v1(21.32,51.71) R60.2@22.16,51.71
NetJ3_15: J3.15 R98.1 R102.1 U30.10 | length 44.8
  Top Layer w0.1: J3.15@45.743,18.276 J3.15@46.209,18.276 ; J3.15@46.205,18.28 J3.15@46.209,18.276 ; v1(46.34,26.61) 46.34,25.736 47.2,24.876 47.2,18.56 46.916,18.276 J3.15@46.209,18.276
  Bottom Layer w0.1: U30.10@33.83,53.56 33.83,52.82 R98.1@34.4,52.25 34.88,52.73 36.36,52.73 R102.1@36.84,52.25 37.62,51.47 37.62,48.564 42.64,43.544 42.64,42.885 43.59,41.935 43.59,33.757 42.535,32.702 42.535,30.703 46.34,26.898 v1(46.34,26.61)
NetJ3_17: J3.17 R96.2 U26.12 | length 61.7
  Top Layer w0.1: U26.12@22.39,58.16 22.39,58.55 v1(22.39,58.68) ; v1(45.98,26.26) 45.98,25.813 47,24.793 47,18.79 46.886,18.676 J3.17@46.209,18.676
  Int2 (Sign) w0.1: v1(22.39,58.68) 22.554,58.516 22.554,56.714 22.34,56.5 22.34,55.425 22.02,55.105 22.02,53.96 22.79,53.19 27.52,53.19 33.582,47.128 33.582,47.095 35.327,45.35 v1(35.61,45.35)
  Int3 (Sign) w0.1: v1(35.61,45.35) 35.61,45.285 35.955,44.94 44.44,44.94 45.37,44.01 45.37,40.47 44.42,39.52 44.42,27.323 45.483,26.26 v1(45.98,26.26)
  Bottom Layer w0.1: v1(22.39,58.68) 22.52,58.68 22.59,58.61 R96.2@22.59,58.02
NetJ5_A5: J5.A5 U28.A1 | length 10.9
  Top Layer w0.1: J5.A5@24.02,65.115 24.02,64.57 24.17,64.42 24.17,61.98 23.79,61.6 23.79,60.86 24.06,60.59 24.06,58.64 24.71,57.99 24.71,55.31 24.9,55.12 U28.A1@24.9,54.92
NetJ5_A8: J5.A8 TP2.1 | length 1.9
  Top Layer w0.1: TP2.1@22.52,63.25 J5.A8@22.52,65.115
NetJ5_B5: J5.B5 U28.B1 | length 24.9
  Top Layer w0.1: J5.B5@22.77,66.415 v1(22.77,67.54) ; v1(24.26,56.6) 24.5,56.36 U28.B1@24.5,54.92
  Int3 (Sign) w0.1: v1(22.77,67.54) 22.25,68.06 18.69,68.06 17.65,67.02 17.65,58.42 19.278,56.792 20.077,56.792 20.385,57.1 23.545,57.1 24.045,56.6 v1(24.26,56.6)
NetJ5_B8: J5.B8 TP3.1 | length 13.3
  Top Layer w0.1: TP3.1@16.42,63.05 16.93,63.56 v1(16.93,63.89) ; J5.B8@24.27,66.415 24.27,67.17 v1(24.47,67.37)
  Int2 (Sign) w0.1: v1(16.93,63.89) 16.93,66.65 18.43,68.15 23.69,68.15 v1(24.47,67.37)
NetJ6_9: J6.9 J6.12 R25.2 | length 17
  Top Layer w0.3: R25.2@94.52,26.48 95.53,26.48 96.95,27.9 J6.12@97.2,27.9 97.45,27.9 98.2,28.65 J6.9@98.2,41.05
NetJ6_10: J6.10 J6.11 R20.1 T1.1 U7.1 | length 24.6
  Top Layer w0.1: T1.1@79.955,30.34 80.55,30.34 v1(80.79,30.58) ; R20.1@81.03,31.4 R20.1@81.03,31.35 81.03,30.82 ; v1(81.89,43.85) 81.89,43.04 U7.1@81.9,43.03 ; v1(80.79,30.58) 81.03,30.82 ; v1(80.79,30.58) 81.03,30.82
  Top Layer w0.2: v1(82.65,33.9) 82.95,33.9 83.07,34.02 84.05,35 J6.11@84.05,35.2
  Top Layer w0.4: v1(83.02,29.5) J6.10@84.05,29.5
  Int2 (Sign) w0.1: v1(80.79,30.58) 81.27,30.58 82.35,29.5 v1(83.02,29.5) 83.86,30.34 83.86,33.22 83.18,33.9 v1(82.65,33.9) 82.13,34.42 82.13,37.039 82.13,43.61 v1(81.89,43.85)
NetJ12_17: J12.17 TP15.1 | length 3.2
  Top Layer w0.1: TP15.1@89.19,17.7 J12.17@92.435,17.7
NetJ12_18: J12.18 TP16.1 | length 3.6
  Top Layer w0.1: TP16.1@89.19,18.94 90.02,18.94 90.76,18.2 J12.18@92.435,18.2
NetJ12_20: J12.20 Q4.2 R50.1 | length 17.3
  Top Layer w0.1: v1(88.63,12.06) 88.61,12.06 88.34,12.33 88.34,19.08 88.9,19.64 91,19.64 91.44,19.2 J12.20@92.435,19.2
  Bottom Layer w0.1: Q4.2@86.985,8.74 88.58,8.74 89.485,9.645 89.485,10.397 89.06,10.822 R50.1@89.06,11.16 89.06,11.63 v1(88.63,12.06)
NetJ12_21: J12.21 Q9.2 R101.1 | length 13.8
  Top Layer w0.1: v1(88.14,11.78) 88.14,19.163 88.817,19.84 91.083,19.84 91.223,19.7 J12.21@92.435,19.7
  Bottom Layer w0.1: Q9.2@86.975,11.2 87.015,11.16 R101.1@88.14,11.16 v1(88.14,11.78)
NetJ12_23: J12.23 TP17.1 | length 3.3
  Top Layer w0.1: TP17.1@89.19,20.53 90.27,20.53 90.44,20.7 J12.23@92.435,20.7
NetJ12_24: J12.24 TP18.1 | length 3.5
  Top Layer w0.1: TP18.1@89.2,21.79 89.84,21.79 90.43,21.2 J12.24@92.435,21.2
NetJ16_L13: J16.L13 R52.2 | length 1.7
  Top Layer w0.1: J16.L13@86.155,49.69 86.155,47.995 R52.2@86.16,47.99
NetJ16_R13: J16.R13 R53.2 | length 2.8
  Top Layer w0.1: J16.R13@72.185,49.69 72.185,49.655 73.88,47.96 74.216,47.96 R53.2@74.247,47.99
NetJ18_20: J18.20 R45.1 | length 67.2
  Top Layer w0.1: R45.1@11.65,9.81 11.66,9.8 12.045,9.8 12.495,10.25 v1(13.05,10.25)
  Int2 (Sign) w0.1: v1(13.05,10.25) 13.07,10.23 14.168,10.23 15.38,10.23 20.33,15.18 37.19,15.18 37.33,15.32 39.76,15.32 41.25,16.81 41.25,17.765 41.25,18.055 41.25,21.885 42.455,23.09 v1(42.71,23.09)
  Int3 (Sign) w0.1: v1(42.71,23.09) 57.89,23.09 62.91,28.11 v1(63.75,28.95)
  Bottom Layer w0.1: J18.20@62.85,26.16 64.01,26.16 64.15,26.3 64.15,28.55 v1(63.75,28.95)
NetJ18_30: J18.30 R55.1 | length 16.7
  Int3 (Sign) w0.1: v1(61.46,22.53) 61.46,23.07 63.79,25.4 63.792,25.4 64.042,25.65 70.21,25.65 70.89,24.97 v1(72.64,24.97)
  Bottom Layer w0.1: v1(61.46,22.53) 61.83,22.16 J18.30@62.85,22.16 ; v1(72.64,24.97) 72.64,25.29 73.46,26.11 R55.1@74.02,26.11
NetJ18_32: J18.32 R56.1 | length 17.7
  Int3 (Sign) w0.1: v1(61.04,22.15) 61.6,22.15 61.811,22.361 61.811,23.139 63.873,25.2 63.875,25.2 64.125,25.45 70.127,25.45 70.807,24.77 70.81,24.77 70.82,24.76 71.88,24.76 v1(72.54,24.1)
  Bottom Layer w0.1: v1(61.04,22.15) 61.04,21.87 61.55,21.36 J18.32@62.85,21.36 ; v1(72.54,24.1) 73.36,24.1 73.45,24.19 R56.1@74.02,24.19
NetJ18_42: J18.42 R57.1 | length 65.9
  Int2 (Sign) w0.1: v1(2.06,11.21) 8.91,11.21 10.81,9.31 12.685,9.31 13.405,10.03 14.25,10.03 15.463,10.03 20.413,14.98 37.09,14.98 37.1,14.97 v1(37.475,14.97)
  Bottom Layer w0.1: v1(2.06,11.21) R57.1@2.06,11.9 ; v1(37.475,14.97) 37.485,14.96 38.278,14.96 38.568,14.67 49.705,14.67 54.09,14.67 56.19,16.77 61.11,16.77 61.7,17.36 J18.42@62.85,17.36
NetJ18_44: J18.44 R58.1 | length 66.3
  Int2 (Sign) w0.1: v1(2.02,9.45) 3.58,11.01 8.827,11.01 10.727,9.11 13.613,9.11 14.334,9.83 15.546,9.83 20.496,14.78 37.007,14.78 37.177,14.61 v1(37.83,14.61)
  Bottom Layer w0.1: v1(2.02,9.45) 2.02,10.07 R58.1@2.05,10.1 ; v1(37.83,14.61) 38.345,14.61 38.485,14.47 49.788,14.47 54.173,14.47 56.263,16.56 J18.44@62.85,16.56
NetJ18_46: J18.46 R59.1 | length 67.1
  Int2 (Sign) w0.1: v1(2.09,7.68) 5.22,10.81 8.744,10.81 10.644,8.91 13.696,8.91 13.81,9.024 14.416,9.63 15.629,9.63 20.579,14.58 36.924,14.58 37.244,14.26 v1(38.2,14.26)
  Bottom Layer w0.1: R59.1@2.06,8.38 2.09,8.35 v1(2.09,7.68) ; v1(38.2,14.26) 54.246,14.26 56.336,16.35 61.14,16.35 61.73,15.76 J18.46@62.85,15.76
NetJ22_17: J22.17 TP11.1 | length 11.7
  Bottom Layer w0.1: TP11.1@6.95,3.41 6.968,3.428 7.478,3.428 8.94,4.89 14.923,4.89 16.26,6.227 J22.17@16.26,7.46
NetJ22_18: J22.18 TP12.1 | length 10.8
  Bottom Layer w0.1: TP12.1@6.95,4.67 8.4,4.67 8.82,5.09 14.84,5.09 15.76,6.01 J22.18@15.76,7.46
NetJ22_20: J22.20 Q7.2 R99.1 | length 31
  Top Layer w0.1: v1(38.82,13.13) 39.05,12.9 39.05,11.684 39.28,11.454 R99.1@39.28,11.03 39.28,10.64 39.18,10.54 Q7.2@39.18,9.995
  Int2 (Sign) w0.1: v1(14.76,8.63) 14.782,8.63 14.982,8.83 15.96,8.83 20.9,13.77 36.602,13.77 37.092,13.28 38.36,13.28 38.51,13.13 v1(38.82,13.13)
  Bottom Layer w0.1: J22.20@14.76,7.46 v1(14.76,8.63)
NetJ22_21: J22.21 Q8.2 R100.1 | length 30.5
  Top Layer w0.1: v1(39.18,13.66) Q8.2@39.18,14.365 39.18,14.95 39.28,15.05 R100.1@39.28,15.42
  Int2 (Sign) w0.1: v1(14.26,8.41) 14.26,8.376 14.278,8.358 14.278,8.41 14.278,8.643 14.41,8.775 14.665,9.03 15.878,9.03 20.827,13.98 36.676,13.98 37.175,13.48 39,13.48 v1(39.18,13.66)
  Bottom Layer w0.1: J22.21@14.26,7.46 v1(14.26,8.41)
NetJ22_23: J22.23 TP13.1 | length 8.1
  Bottom Layer w0.1: TP13.1@6.95,5.93 8.15,5.93 8.78,5.3 12.1,5.3 13.26,6.46 J22.23@13.26,7.46
NetJ22_24: J22.24 TP14.1 | length 8
  Bottom Layer w0.1: TP14.1@6.95,7.19 7.088,7.052 7.478,7.052 9.03,5.5 12.017,5.5 12.76,6.243 J22.24@12.76,7.46
NetL1_2: L1.2 U5.8 | length 2
  Bottom Layer w0.254: U5.8@30.575,50.36 30.682,50.253 30.682,50.165 32.41,50.165 L1.2@32.43,50.185
NetL2_2: L2.2 U5.5 | length 2
  Bottom Layer w0.254: L2.2@24.88,50.185 24.915,50.22 26.765,50.22 U5.5@26.765,50.36
NetL16_1: L16.1 T5.3 | length 6.8
  Bottom Layer w0.4: T5.3@74.4,38.29 74.4,37.34 75.1,36.64 75.1,33.55 75.5,33.15 L16.1@76.7,33.15
NetL24_1: L24.1 U21.4
NetL24_2: L24.2 U21.2
NetL25_1: L25.1 U22.5
NetLED1_1: LED1.1 R57.2 | length 1.5
  Top Layer w0.1: v1@0.89,12.58 v1(0.96,12.58) 0.96,11.895 LED1.1@0.955,11.89
  Bottom Layer w0.1: v1(0.96,12.58) 0.96,11.95 R57.2@1.01,11.9
NetLED2_1: LED2.1 R58.2 | length 1.7
  Top Layer w0.1: v1(0.95,10.9) 0.95,10.105 LED2.1@0.955,10.1
  Bottom Layer w0.1: v1@0.88,10.9 0.83,10.9 0.95,10.78 R58.2@0.95,10.1
NetLED3_1: LED3.1 R59.2 | length 1.4
  Top Layer w0.1: LED3.1@0.955,8.38 v1(0.955,9.1)
  Bottom Layer w0.1: v1(0.955,9.1) 0.96,9.095 R59.2@0.96,8.38
NetQ1_1: Q1.1 Q2.3 R3.1 | length 5.8
  Top Layer w0.1: Q2.3@13.37,23.435 13.37,24.13 13.01,24.49 11.92,24.49 v1(11.49,24.92) ; v1(11.49,24.92) 11.49,25.004 Q1.1@11.49,25.575 v1(11.49,24.92)
  Bottom Layer w0.1: R3.1@10.23,25.675 10.695,25.675 11.45,24.92 v1(11.49,24.92)
NetQ1_3: Q1.3 R4.1 R10.1 | length 47.7
  Top Layer w0.1: v1(10.19,27.41) 10.19,26.538 10.84,25.888 Q1.3@10.84,23.425 Q1.3@10.84,23.3 ; v1(10.83,22.61) Q1.3@10.83,23.3 ; v1(33.71,49.16) R10.1@34.26,49.16
  Int3 (Sign) w0.1: v1(10.19,27.41) 10.271,27.41 10.421,27.26 19.903,27.26 20.96,28.317 20.96,41.314 22.026,42.38 24,42.38 26.77,45.15 31.813,45.15 33.43,46.767 33.43,48.88 v1(33.71,49.16)
  Bottom Layer w0.1: R4.1@10.23,22.615 10.25,22.595 10.265,22.61 v1(10.83,22.61)
NetQ5_1: Q5.1 R79.2 | length 1.6
  Top Layer w0.2: R79.2@24.01,48.25 24.01,49.11 24.15,49.25 Q5.1@24.7,49.25
NetQ5_3: Q5.3 R73.2 U22.3 | length 3.5
  Top Layer w0.1: U22.3@20.61,48.035 21.235,48.035 21.44,48.24 R73.2@21.95,48.24 ; R73.2@21.9,48.24 21.9,48.61 22.755,49.465 Q5.3@22.755,49.92
NetQ6_3: Q6.3 R89.1 | length 1.6
  Top Layer w0.1: R89.1@31.72,56.635 32.295,56.06 Q6.3@33.075,56.06
NetR10_2: R10.2 U6.26 | length 2
  Top Layer w0.1: R10.2@35.31,49.16 35.771,49.16 36.04,49.43 36.5,49.89 U6.26@37,49.89
NetR13_2: R13.2 U6.35 | length 2.3
  Top Layer w0.1: U6.35@41.5,48.39 41.5,47.879 41.71,47.67 R13.2@43.25,47.67
NetR14_2: R14.2 U6.11 | length 1.6
  Top Layer w0.1: U6.11@41.5,54.34 41.5,54.39 41.5,55.2 41.71,55.41 R14.2@42.2,55.41
NetR15_2: R15.2 U6.22 | length 2
  Top Layer w0.1: R15.2@35.325,52.675 35.735,52.675 36.13,52.28 36.52,51.89 U6.22@37,51.89
NetR16_2: R16.2 U6.24 | length 1.7
  Top Layer w0.1: R16.2@35.3,50.95 35.98,50.95 36.04,50.89 U6.24@37,50.89
NetR17_2: R17.2 U6.25 | length 1.8
  Top Layer w0.1: R17.2@35.3,50.05 35.8,50.05 36.14,50.39 U6.25@37,50.39
NetR18_2: R18.2 U6.28 | length 3.3
  Top Layer w0.1: R18.2@35.76,47.15 35.76,47.56 35.95,47.75 37.9,47.75 38,47.85 U6.28@38,48.39
NetR27_1: R27.1 T3.3 | length 1.9
  Bottom Layer w0.1: T3.3@78.33,34.95 78.33,36.13 R27.1@78.83,36.63
NetR28_1: R28.1 T3.1 T4.3 | length 6.2
  Bottom Layer w0.1: R28.1@77.64,30.56 77.64,31.411 77.699,31.47 78.205,31.976 78.205,32.315 T4.3@78.33,32.44 ; T4.3@78.205,32.44 78.205,33.575 80.005,35.375 T3.1@80.23,35.6
NetR34_2: R34.2 U11.11 | length 1.6
  Bottom Layer w0.254: R34.2@42.09,27.91 42.09,27.46 42.355,27.195 U11.11@42.355,26.44
NetR35_2: R35.2 U11.12 | length 1.5
  Bottom Layer w0.254: U11.12@43.005,26.44 R35.2@43.005,27.91
NetR36_2: R36.2 R43.1 U11.13 | length 49.4
  Top Layer w0.1: v1(6.245,9.81) R43.1@6.57,9.81
  Int2 (Sign) w0.1: v1(6.245,9.81) 7.05,9.81 8.35,8.51 13.862,8.51 14.21,8.858 14.582,9.23 15.795,9.23 20.744,14.18 36.759,14.18 37.253,13.686 38.706,13.686 41.66,16.64 41.66,20.287 42.72,21.346 v1(42.72,22.27)
  Bottom Layer w0.1: v1(42.72,22.27) 43.008,21.983 43.008,20.542 U11.13@43.005,20.54 ; U11.13@42.995,20.47 43.005,20.46 43.005,19.015 R36.2@43.01,19.01
NetR37_2: R37.2 R44.1 U11.14 | length 45.6
  Top Layer w0.1: v1(8.58,9.84) 8.61,9.81 R44.1@9.11,9.81
  Int2 (Sign) w0.1: v1(8.58,9.84) 9.431,9.84 10.561,8.71 13.779,8.71 14.01,8.941 14.499,9.43 15.712,9.43 20.661,14.38 36.841,14.38 37.336,13.886 38.623,13.886 41.46,16.723 41.46,20.38 42.34,21.26 v1(42.34,21.58)
  Bottom Layer w0.1: R37.2@42.12,19.01 42.12,19.48 42.355,19.715 U11.14@42.355,20.54 ; v1(42.34,21.58) 42.345,21.575 U11.14@42.345,20.47
NetR40_2: R40.2 R41.2 U11.8 | length 7.7
  Top Layer w0.127: R40.2@38.925,20.036 R41.2@39.815,20.036 40.71,20.931 40.71,25.06 40.41,25.36 v1(40.41,25.35)
  Bottom Layer w0.127: U11.8@40.395,26.37 40.395,25.365 v1(40.41,25.35)
NetR43_2: R43.2 SW1.1 | length 1.8
  Top Layer w0.1: R43.2@6.83,10.695 SW1.1@6.83,12.45
NetR44_2: R44.2 SW1.2 | length 1.5
  Top Layer w0.1: R44.2@9.37,10.91 SW1.2@9.37,12.45
NetR45_2: R45.2 SW1.3 | length 1.5
  Top Layer w0.1: R45.2@11.91,10.91 SW1.3@11.91,12.45
NetR46_1: R46.1 R47.1 T6.3 | length 3.1
  Bottom Layer w0.1: T6.3@78.305,38.3 78.305,39.565 78.48,39.74 R47.1@78.48,40.39
  Bottom Layer w0.127: R47.1@78.48,40.39 R46.1@78.48,41.36
NetR48_2: R48.2 T6.1 | length 0.9
  Bottom Layer w0.127: T6.1@80.455,38.95 80.455,39.815 R48.2@80.47,39.83
NetR64_1: R64.1 R67.2 U21.10 | length 2.5
  Top Layer w0.254: U21.10@20.28,54.24 20.28,54.54 20.676,54.936 20.676,55.458 R64.1@20.674,55.46 20.676,55.462 20.676,56.538 R67.2@20.674,56.54
NetR65_2: R65.2 U21.6 | length 1.6
  Top Layer w0.25: U21.6@20.535,52.24 21.43,52.24 21.69,51.98 R65.2@22.04,51.98
NetR66_2: R66.2 U21.7 | length 1.8
  Top Layer w0.2: U21.7@20.28,52.74 20.708,52.74
  Top Layer w0.35: 20.708,52.74 R66.2@22.04,52.74
NetR68_1: R68.1 R69.1 R70.1 T12.2 | length 6.7
  Top Layer w0.1: R69.1@10.38,67.56 R70.1@9.44,67.56 R68.1@8.51,67.56 8.5,67.57 8.5,70.15 7.7,70.95 T12.2@7.2,70.95 ; T12.2@7.2,70.95 6.9,70.95 T12.2@7.2,70.95
NetR71_2: R71.2 U22.8 | length 1.4
  Top Layer w0.2: U22.8@17.72,46.735 17.72,46.39 R71.2@18.46,45.65
NetR72_1: R72.1 R77.2 U22.7 | length 2.5
  Top Layer w0.2: v1(16.97,47.38) 16.975,47.385 U22.7@17.61,47.385
  Bottom Layer w0.2: R72.1@16.41,46.51 R77.2@17.27,46.51 17.27,47.08 v1(16.97,47.38)
NetR74_2: R74.2 U22.6 | length 3.3
  Top Layer w0.1: v1@16.98,48.035 U22.6@17.61,48.035 ; v1@17.07,49.88 R74.2@17.93,49.88
  Int3 (Sign) w0.1: v1(16.98,48.03) v1(16.98,49.88)
NetR75_2: R75.2 U22.1 | length 1.6
  Top Layer w0.1: U22.1@20.61,46.735 21.165,46.735 21.66,46.24 21.91,46.24 R75.2@21.95,46.2
NetR83_2: R83.2 U23.3 | length 1.3
  Bottom Layer w0.305: R83.2@74.64,13.65 74.99,13.3 75.7,13.3 75.7,13.33 U23.3@75.73,13.36
NetR86_2: R86.2 U24.3 | length 1.4
  Top Layer w0.2: R86.2@10.77,26.72 U24.3@12.12,26.72
NetR89_2: R89.2 R90.2 U29.A3 | length 7.5
  Top Layer w0.1: v1(27.06,59.66) 27.06,59.579 27.16,59.479 27.16,59.255 27.26,59.155 27.26,58.65 U29.A3@27.59,58.32 ; v1(29.71,56.62) 29.75,56.62 29.77,56.64 29.775,56.635 R89.2@30.62,56.635 R90.2@30.62,55.715
  Int3 (Sign) w0.1: v1(27.06,59.66) 27.06,59.27 27.26,59.07 v1(29.71,56.62)
NetR93_1: R93.1 R94.1 U30.5 | length 2.5
  Bottom Layer w0.1: U30.5@34.23,55.96 34.435,55.96 34.865,55.96 35.93,55.96 R93.1@35.94,55.97 36.74,55.97 R94.1@36.75,55.98
NetR95_1: R95.1 U26.3 | length 4
  Top Layer w0.1: v1(21.43,55.17) 21.87,55.17 22.12,55.42 22.12,56.15 22.39,56.42 U26.3@22.39,56.76
  Bottom Layer w0.1: R95.1@20.36,54.27 20.36,54.72 20.81,55.17 v1(21.43,55.17)
NetR97_1: R97.1 U30.16 | length 1.2
  Bottom Layer w0.1: R97.1@31.16,55.45 31.46,55.45 31.75,55.16 U30.16@32.23,55.16
NetTP4_1: TP4.1 U29.B1 U29.B2 U29.C1 | length 3.4
  Top Layer w0.1: U29.C1@28.59,57.32 28.9,57.01 29.52,57.01 30.04,57.53 TP4.1@30.67,57.53
  Top Layer w0.25: U29.B2@28.09,57.82 U29.B1@28.09,57.32 U29.C1@28.59,57.32
NetTP5_1: TP5.1 U28.C3 | length 1.3
  Top Layer w0.1: TP5.1@23.95,52.85 24.1,53 U28.C3@24.1,54.12
NetTP6_1: TP6.1 U30.2 | length 4
  Top Layer w0.1: v1(33.03,56.68) 33.342,56.68 34.22,55.802 TP6.1@34.22,54.1
  Bottom Layer w0.1: U30.2@33.03,55.96 v1(33.03,56.68)
NetTP7_1: TP7.1 U30.9 | length 2.4
  Top Layer w0.1: v1(35.27,53.77) 35.68,54.18 TP7.1@36.29,54.18
  Bottom Layer w0.1: U30.9@34.23,53.56 34.23,53.53 34.3,53.46 34.96,53.46 v1(35.27,53.77)
POWERIN: J19.3 L23.1
RTS_B_RS232: J10.4 U11.7 | length 14.2
  Int2 (Sign) w0.1: J10.4@30.46,19.75 31.71,21 37.935,21 39.486,22.551 39.486,25.076 v1(39.76,25.35)
  Bottom Layer w0.1: U11.7@39.755,26.44 39.755,25.385 39.76,25.38 v1(39.76,25.35)
RXA: J9.3 U10.8 | length 24.7
  Int3 (Sign) w0.1: J9.3@30.44,12.77 31.93,14.26 33.988,14.26 35.68,15.952 35.68,18.693 35.41,18.964 35.41,32.464 35.26,32.614 v1(35.26,32.93) 35.36,32.93 v1@35.41,32.88
  Bottom Layer w0.1: v1(35.26,32.93) 35.26,32.95 35.28,32.93 U10.8@36.055,32.93
RXC: J8.3 U10.13 | length 13.2
  Int2 (Sign) w0.1: J8.3@30.54,31.77 32.37,33.6 36.313,33.6 36.955,33.6 38.65,35.295 38.65,35.925 38.65,36.215 v1(38.65,36.44)
  Bottom Layer w0.1: v1(38.65,36.44) 38.65,36.74 38.655,36.745 U10.13@38.655,38.88
RXD_B_RS232: J10.3 U11.16 | length 13
  Bottom Layer w0.1: J10.3@30.44,22.27 31.8,23.63 37.53,23.63 38.82,22.34 40.08,22.34 40.878,21.542 41.045,21.375 U11.16@41.045,20.47
S_TX1_N: C94.2 U26.7 | length 1.5
  Top Layer w0.193: U26.7@23.69,57.26 23.743,57.313 24.127,57.313 v1(24.23,57.21)
  Bottom Layer w0.193: v1(24.23,57.21) 24.323,57.303 24.712,57.303 C94.2@24.98,57.034
S_TX1_P: C93.2 U26.8 | length 1.5
  Top Layer w0.193: U26.8@23.69,57.66 23.743,57.607 24.127,57.607 v1(24.23,57.71)
  Bottom Layer w0.193: v1(24.23,57.71) 24.344,57.596 24.712,57.596 C93.2@24.98,57.864
S_TX2_N: C96.2 U26.6 | length 4
  Top Layer w0.193: v1(22.88,55.455) 22.936,55.455 23.039,55.558 23.238,55.558 23.537,55.857 23.537,56.219 23.537,56.569 23.562,56.594 23.562,56.732 U26.6@23.59,56.76
  Bottom Layer w0.193: v1(22.88,55.455) 22.936,55.455 23.039,55.558 24.684,55.558 24.747,55.496 24.747,55.478 24.96,55.265 C96.2@24.98,55.265
S_TX2_P: C95.2 U26.5 | length 3.5
  Top Layer w0.193: v1(22.88,55.955) 22.936,55.955 23.039,55.851 23.116,55.851 23.243,55.978 23.243,56.097 23.243,56.569 23.218,56.594 23.218,56.732 U26.5@23.19,56.76
  Bottom Layer w0.193: v1(22.88,55.955) 22.936,55.955 23.039,55.851 24.684,55.851 24.747,55.914 24.747,55.931 24.96,56.145 C95.2@24.98,56.145
SD_A_VSEL: J2.54 TP26.1 | length 2.6
  Top Layer w0.1: J2.54@54.34,42.23 54.34,40.933 v1(54.59,40.683)
  Bottom Layer w0.1: TP26.1@54.26,39.87 54.305,39.915 54.305,40.398 v1(54.59,40.683)
SPI_C_MISO: J2.85 TP20.1 | length 3
  Top Layer w0.1: TP20.1@47.75,48.31 47.75,46.64 47.94,46.45 J2.85@47.94,45.41
SPI_C_MOSI: J2.87 TP21.1 | length 3.3
  Top Layer w0.1: TP21.1@46.49,48.31 46.49,47.47 47.54,46.42 J2.87@47.54,45.41
SPI_C_SCLK: J2.89 TP22.1 | length 3.7
  Top Layer w0.1: TP22.1@45.23,48.33 47.14,46.42 J2.89@47.14,45.41
SPI_C_SS0: J2.83 TP19.1 | length 3.2
  Top Layer w0.1: J2.83@48.34,45.41 48.34,46.59 49.01,47.26 TP19.1@49.01,48.31
SS_RX1_N: U26.1 U27.C2 | length 7.2
  Top Layer w0.193: U27.C2@19.602,59.737 19.602,59.722 19.549,59.668 19.549,59.249 19.652,59.146 v1(19.652,59.09) ; v1(21.21,55.92) 21.21,55.976 21.33,56.096 21.33,56.17 21.64,56.48 21.64,56.71 U26.1@21.59,56.76
  Int2 (Sign) w0.1: v1(19.652,59.09) 19.652,59.171 19.554,59.269 19.554,59.334 19.699,59.478 20.852,59.478 21.333,58.997 21.333,56.513 21.334,56.511 21.334,56.102 ; v1(21.21,55.92) 21.21,55.975 21.338,56.102
SS_RX1_P: U26.2 U27.C1 | length 8.1
  Top Layer w0.193: v1(19.152,59.09) 19.152,59.146 19.256,59.249 19.256,59.668 19.202,59.722 U27.C1@19.202,59.737 ; v1(21.72,55.92) 21.72,55.976 21.635,56.06 21.94,56.365 21.94,56.71 U26.2@21.99,56.76
  Int2 (Sign) w0.1: v1(19.152,59.09) 19.152,59.132 19.292,59.272 19.292,59.442 19.59,59.74 20.96,59.74 21.594,59.106 21.594,56.621 21.596,56.62 21.596,56.102 ; 21.592,56.102 21.72,55.975 v1(21.72,55.92)
SS_RX2_N: U26.16 U27.C4 | length 8.3
  Top Layer w0.193: v1(19.23,57.43) 19.286,57.43 19.389,57.533 20.616,57.533 20.836,57.313 21.299,57.313 21.324,57.288 21.462,57.288 U26.16@21.49,57.26 ; U27.C4@20.402,59.737 20.402,59.722 20.349,59.668 20.349,59.456 20.744,59.061 20.744,58.699 20.847,58.596 v1(20.847,58.54)
  Int2 (Sign) w0.1: v1(19.23,57.43) 19.293,57.43 19.412,57.549 19.491,57.549 19.73,57.31 19.73,56.69 20.032,56.388 20.458,56.388 20.728,56.658 20.728,58.358 20.847,58.477 v1(20.847,58.54)
SS_RX2_P: U26.15 U27.C3 | length 7.9
  Top Layer w0.193: v1(19.23,57.93) 19.286,57.93 19.389,57.827 20.737,57.827 20.957,57.607 21.299,57.607 21.324,57.632 21.462,57.632 U26.15@21.49,57.66 ; U27.C3@20.002,59.737 20.002,59.722 20.056,59.668 20.056,59.334 20.45,58.94 20.45,58.699 20.347,58.596 v1(20.347,58.54)
  Int2 (Sign) w0.1: v1(19.23,57.93) v1@19.323,57.837 ; v1@19.266,57.78 v1@19.323,57.837 ; v1(20.347,58.54) 20.347,58.477 20.466,58.358 20.466,56.766 20.35,56.65 20.14,56.65 19.992,56.798 19.992,57.418 19.599,57.811 19.412,57.811 19.36,57.864 19.349,57.864 v1@19.323,57.837
SS_TX1_N: C94.1 U25.C3 | length 5.7
  Top Layer w0.193: U25.C3@25.19,59.77 25.19,59.755 25.243,59.701 25.243,59.065 25.618,58.69 26.313,58.69 26.43,58.573 26.43,58.485 26.318,58.373 26.064,58.373 25.75,58.06 25.75,57.65 26.04,57.36 26.601,57.36 26.754,57.207 v1(26.81,57.207)
  Bottom Layer w0.193: C94.1@26.06,57.034 26.336,57.31 26.707,57.31 v1(26.81,57.207) v1@26.754,57.207
SS_TX1_P: C93.1 U25.C4 | length 5.1
  Top Layer w0.193: U25.C4@25.59,59.77 25.59,59.755 25.537,59.701 25.537,59.187 25.74,58.984 26.434,58.984 26.723,58.695 26.723,58.363 26.44,58.08 26.185,58.08 26.043,57.938 26.043,57.772 26.161,57.654 26.611,57.654 26.624,57.667 26.77,57.667 v1(26.81,57.707)
  Bottom Layer w0.193: C93.1@26.06,57.864 26.321,57.604 26.707,57.604 v1(26.81,57.707)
